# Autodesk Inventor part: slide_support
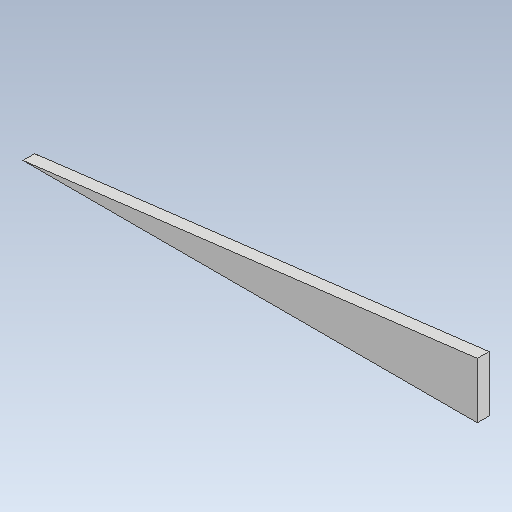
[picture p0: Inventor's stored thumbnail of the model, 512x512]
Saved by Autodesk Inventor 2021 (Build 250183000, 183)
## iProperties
Created: 2026-10
Part Number: slide_support
Material: Generic
Document SubType Name: Modeling
Designer: alolo
Density: 1 g/cm^3
Appearance: Default
Author: alolo
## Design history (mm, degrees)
sketch "Sketch1"
  geometry: L1 (0, 0)-(193.546, 0); L2 (193.546, 0)-(193.546, 23.765); L3 (0, 0)-(193.546, 23.765)
  constraints: 6 end point, 1 horizontal, 1 perpendicular
  dimensions: "d0" = 195 distance of L1.start L2.end (= slide_length); "d1" = 7 deg angle of L1 L3 (= slide_angle)
extrude "Extrusion1" new body sketch "Sketch1" distance "d2" = 5 (= wood_thickness); taper "d3" = 0 deg
body "Solid1"
other parameters: "slide_length" = 195 [user parameter; used in 1 equation term], "slide_angle" = 7 deg [user parameter; used in 1 equation term], "slide_width" = 65 [user parameter], "wood_thickness" = 5 [user parameter; used in 1 equation term], "aclyric_thickness" = 6 [user parameter]
